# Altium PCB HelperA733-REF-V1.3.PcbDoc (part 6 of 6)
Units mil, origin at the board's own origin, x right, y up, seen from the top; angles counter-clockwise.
Board outline 5905.51 x 4133.86 mil, 2 copper layers (Top, Bottom), stack 12.7 mil thick; 446 components, 341 nets, 1706 pads, 1667 vias.
Unrouted connection lines stored in the file: 1382.
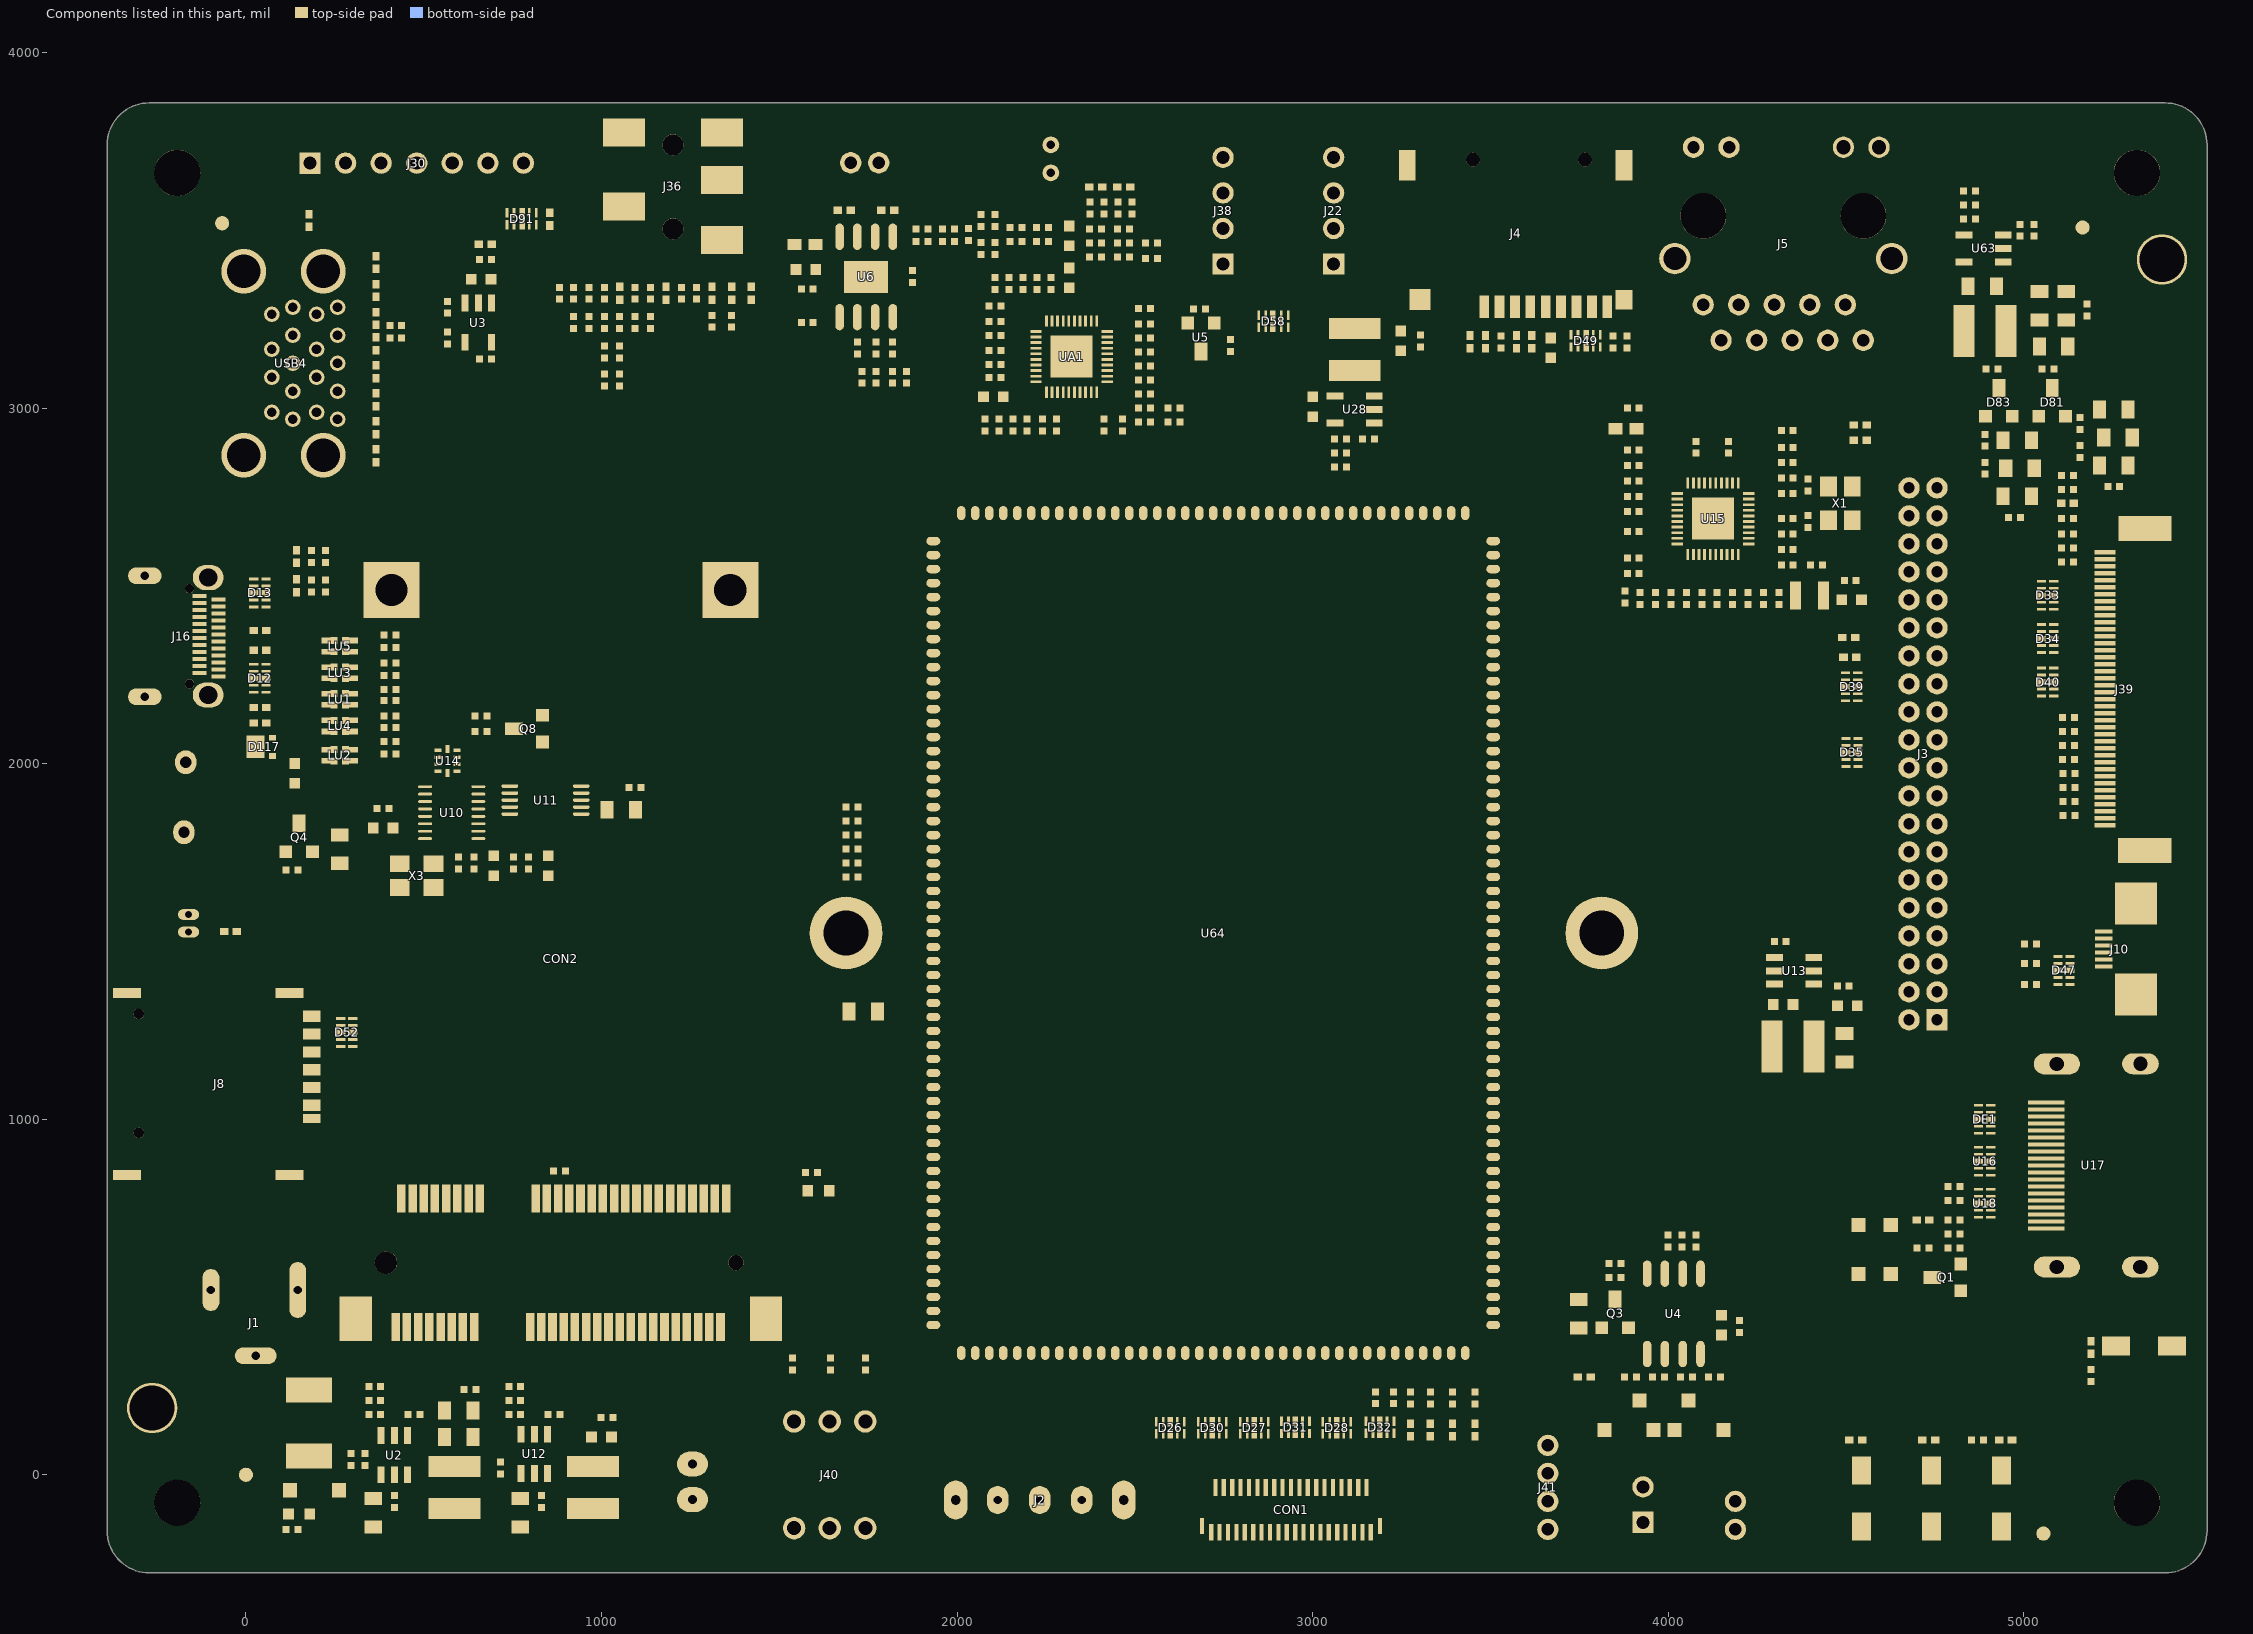
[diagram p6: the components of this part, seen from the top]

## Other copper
Top:
  region net DCIN: 433.07,19.69 429.13,23.62 401.57,23.62 397.64,19.69 397.64,-27.56 393.7,-31.5 314.96,-31.5 267.72,15.75 267.72,86.61 263.78,90.55 114.17,90.55 110.24,86.61 110.24,0 114.17,-3.94 204.72,-3.94 208.66,-7.87 208.66,-82.68 212.6,-86.61 385.83,-86.61 401.57,-70.87 429.13,-70.87 433.07,-66.93 433.07,19.69
  region net 5V: 688.64,900.16 688.64,845.23 748.73,845.23 748.73,900.16 688.64,900.16
  region net VCC-3V3: 3047.24,3192.91 3314.96,3192.91 3318.9,3196.85 3318.9,3255.91 3314.96,3259.84 3047.24,3259.84 3043.31,3255.91 3043.31,3196.85 3047.24,3192.91
  region net N17914651: 4918.31,3417.32 4918.31,3407.42 4957.1,3368.63 4957.1,3307.15 4918.31,3268.36 4918.31,3102.36 4922.24,3098.43 5060.04,3098.43 5063.98,3102.36 5063.98,3200.79 5060.04,3204.72 4997.05,3204.72 4993.11,3208.66 4993.11,3417.32 4989.17,3421.26 4922.24,3421.26 4918.31,3417.32
  region net 5V: 694.25,624.85 694.25,575.69 748.95,575.69 748.95,624.85 694.25,624.85
  region net REGOUT: 4195.66,2607.02 4191.66,2603.02 4191.66,2531.02 4207.66,2515.02 4315.66,2515.02 4331.66,2499.02 4331.66,2435.02 4335.66,2431.02 4367.66,2431.02 4371.66,2435.02 4371.66,2535.02 4363.66,2543.02 4233.66,2543.02 4223.66,2553.02 4223.66,2603.02 4219.66,2607.02 4195.66,2607.02
  region net N17914691: 4863.19,2992.13 4863.19,2917.32 4867.13,2913.39 4914.37,2913.39 4918.31,2909.45 4918.31,2885.83 4922.24,2881.89 4957.68,2881.89 4961.61,2885.83 4961.61,2940.94 4957.68,2944.88 4926.18,2944.88 4922.24,2948.82 4922.24,2992.13 4918.31,2996.06 4867.13,2996.06 4863.19,2992.13
  region net VCC-1V8: 2634.84,3295.15 2630.84,3291.15 2630.84,3223.15 2634.84,3219.15 2676.01,3219.15 2680.01,3223.15 2680.01,3291.15 2676.01,3295.15 2634.84,3295.15
  region net N5679088: 440.94,19.69 440.94,-122.05 444.88,-125.98 657.48,-125.98 661.42,-122.05 661.42,-66.93 657.48,-62.99 503.94,-62.99 500,-59.06 500,19.69 496.06,23.62 444.88,23.62 440.94,19.69
  region net AVDD10: 4423.66,2518.61 4419.66,2514.61 4419.66,2435.02 4423.66,2431.02 4503.66,2431.02 4507.66,2435.02 4507.66,2531.02 4503.66,2535.02 4475.66,2535.02 4471.66,2531.02 4471.66,2503.02 4467.66,2499.02 4463.66,2499.02 4459.66,2503.02 4459.66,2514.61 4455.66,2518.61 4423.66,2518.61
  region net VGH: 5142.72,2944.88 5142.72,2885.83 5146.65,2881.89 5189.96,2881.89 5193.9,2877.95 5193.9,2771.65 5197.83,2767.72 5245.08,2767.72 5249.02,2771.65 5249.02,2944.88 5245.08,2948.82 5146.65,2948.82 5142.72,2944.88
  region net N16925291: 4436,1388 4432,1392 4384,1392 4380,1388 4380,1132 4384,1128 4516,1128 4520,1132 4520,1188 4516,1192 4440,1192 4436,1196 4436,1388
  region net 5V: 4863.19,3145.67 4863.19,3417.32 4859.25,3421.26 4804.13,3421.26 4800.2,3417.32 4800.2,3145.67 4804.13,3141.73 4859.25,3141.73 4863.19,3145.67
  region net N17680063: 3149.61,3023.62 3153.54,3019.69 3192.91,3019.69 3196.85,3023.62 3196.85,3133.86 3192.91,3137.8 3047.24,3137.8 3043.31,3133.86 3043.31,3070.87 3047.24,3066.93 3145.67,3066.93 3149.61,3062.99 3149.61,3023.62
  region net VCC_4G: 905.51,-7.87 1295.28,-7.87 1299.21,-3.94 1299.21,350.39 1295.28,354.33 1133.86,354.33 1129.92,350.39 1129.92,181.1 1125.98,177.17 1023.62,177.17 1019.68,173.23 1019.68,129.92 1011.81,122.05 1011.81,66.93 1007.87,62.99 905.51,62.99 901.57,59.06 901.57,-3.94 905.51,-7.87
  region net VBUS-USB: 519.68,1803.15 523.62,1807.09 523.62,1814.96 519.68,1818.9 460.63,1818.9 437.01,1842.52 437.01,1874.02 417.32,1893.7 393.7,1893.7 389.76,1889.76 389.76,1807.09 393.7,1803.15 519.68,1803.15
  region net LED+: 5259.45,1851.32 5257.45,1853.32 5207.45,1853.32 5205.45,1851.32 5205.45,1811.32 5207.45,1809.32 5257.45,1809.32 5259.45,1811.32 5259.45,1851.32
  region net N17914681: 5071.85,3122.05 5071.85,3094.49 5060.04,3082.68 5060.04,3035.43 5063.98,3031.5 5119.09,3031.5 5123.03,3035.43 5123.03,3122.05 5119.09,3125.98 5075.79,3125.98 5071.85,3122.05
  region net VCC_4G: 1136.38,452.21 1136.38,379.56 1186.82,379.56 1186.82,452.21 1136.38,452.21
  region net N17914762: 5095.66,2991.02 5095.66,2964.34 5100,2960 5228,2960 5235.66,2967.66 5235.66,3019.02 5231.66,3023.02 5195.66,3023.02 5191.66,3019.02 5191.66,2999.02 5187.66,2995.02 5099.66,2995.02 5095.66,2991.02
  region net AVDD: 5079.72,3149.61 5083.66,3145.67 5189.96,3145.67 5193.9,3149.61 5193.9,3196.85 5189.96,3200.79 5154.53,3200.79 5150.59,3204.72 5150.59,3212.6 5154.53,3216.54 5189.96,3216.54 5193.9,3220.47 5193.9,3271.65 5016.73,3271.65 5012.8,3267.72 5012.8,3216.54 5016.73,3212.6 5075.79,3212.6 5079.72,3208.66 5079.72,3149.61
  region net LED+: 4456,1220 4548,1220 4552,1224 4552,1388 4548,1392 4508,1392 4504,1388 4504,1288 4500,1284 4456,1284 4452,1280 4452,1224 4456,1220
  region net AVDD33: 4039.66,2755.02 4043.66,2759.02 4043.66,2791.02 4039.66,2795.02 3992.98,2795.02 3960,2828 3960,2960 3956.98,2963.02 3887.66,2963.02 3883.66,2959.02 3883.66,2919.02 3908.15,2894.54 3908.15,2785.3 3910.42,2783.02 3919.66,2783.02 3947.66,2755.02 4039.66,2755.02
  region net 5V-IN: 1751.97,1275.59 1795.28,1275.59 1799.21,1279.53 1799.21,1377.95 1795.28,1381.89 1751.97,1381.89 1748.03,1377.95 1748.03,1279.53 1751.97,1275.59
  region net VBUS-USB: 94.49,2082.68 90.55,2086.61 66.93,2086.61 62.99,2082.68 62.99,1897.64 66.93,1893.7 153.54,1893.7 157.48,1897.64 157.48,1964.57 153.54,1968.5 98.43,1968.5 94.49,1972.44 94.49,2082.68
  region net VBUS1: 676.13,3275.59 680.07,3271.65 716.54,3271.65 720.47,3275.59 720.47,3472.44 716.54,3476.38 680.07,3476.38 676.13,3472.44 676.13,3275.59
  region net 5V: 515.75,66.93 511.81,62.99 511.81,-3.94 515.75,-7.87 677.17,-7.87 681.1,-3.94 681.1,251.97 677.17,255.91 637.8,255.91 633.86,251.97 633.86,228.35 594.49,188.98 594.49,70.87 590.55,66.93 515.75,66.93
  region net N179147341: 4863.19,3122.05 4863.19,3035.43 4867.13,3031.5 4949.8,3031.5 4953.74,3035.43 4953.74,3078.74 4949.8,3082.68 4910.43,3082.68 4906.5,3086.61 4906.5,3122.05 4902.56,3125.98 4867.13,3125.98 4863.19,3122.05
  region net N5680029: 102.36,200.79 240.16,200.79 244.09,204.72 244.09,602.36 240.16,606.3 102.36,606.3 98.43,602.36 98.43,204.72 102.36,200.79
  region net 5V: 3084,3016 3088,3020 3088,3056 3084,3060 3036,3060 3032,3064 3032,3100 3028,3104 2975.82,3104 2974.15,3102.33 2974.15,3024.9 2983.05,3016 3084,3016
  region net VGL: 4863.19,2901.57 4863.19,2838.58 4867.13,2834.65 4910.43,2834.65 4914.37,2830.71 4914.37,2681.1 4918.31,2677.17 4965.55,2677.17 4969.49,2681.1 4969.49,2866.14 4965.55,2870.08 4910.43,2870.08 4906.5,2874.02 4906.5,2901.57 4902.56,2905.51 4867.13,2905.51 4863.19,2901.57
  region net 5V: 1716.54,1336.06 1712.6,1340 1622.05,1340 1618.11,1336.06 1618.11,1259.94 1622.05,1256 1712.6,1256 1716.54,1259.94 1716.54,1336.06
  region net 5V: 2988.7,3193.77 2988.7,3121.77 3016.7,3121.77 3016.7,3193.77 2988.7,3193.77
  region net 5V: 4324,1388 4320,1392 4212,1392 4208,1388 4208,1132 4212,1128 4320,1128 4324,1132 4324,1388
  region net 5V-IN: 1917.32,1417.32 1917.32,1354.33 1921.26,1350.39 1976.38,1350.39 1980.31,1354.33 1980.31,1417.32 1976.38,1421.26 1921.26,1421.26 1917.32,1417.32
  region net DCIN: 680,-224 680,-248 756,-248 756,-224 680,-224
  region net DCIN: 830.71,27.56 826.77,31.5 795.28,31.5 791.34,27.56 791.34,-31.5 787.4,-35.43 695.94,-35.43 692,-39.37 692,-86.61 695.94,-90.55 807.09,-90.55 811.02,-86.61 811.02,-74.8 814.96,-70.87 842.52,-70.87 846.46,-66.93 846.46,-47.24 830.71,-31.5 830.71,27.56
  region net 5V: 681.1,3212.6 677.17,3208.66 677.17,3091.94 681.1,3088 740.09,3088 744.03,3091.94 744.03,3208.66 740.09,3212.6 681.1,3212.6
  region net N17177143: 838.58,27.56 838.58,-25.52 854.33,-41.27 854.33,-122.05 858.27,-125.98 1047.24,-125.98 1051.18,-122.05 1051.18,-66.93 1047.24,-62.99 893.7,-62.99 889.76,-59.06 889.76,27.56 885.83,31.5 842.52,31.5 838.58,27.56
Bottom:
  region net AVDD33: 3970.77,2953.26 3966.77,2957.26 3906.77,2957.26 3902.77,2953.26 3902.77,2841.26 3906.77,2837.26 3966.77,2837.26 3970.77,2841.26 3970.77,2953.26
  region net 5V: 691.98,648.04 691.98,581.49 749.2,581.49 749.2,648.04 691.98,648.04
  region net 5V: 708,3216 708,3096 712,3092 744,3092 748,3096 748,3172 752,3176 752,3216 748,3220 712,3220 708,3216
  region net 5V: 4196,1388 4196,1312 4200,1308 4268,1308 4272,1312 4272,1388 4268,1392 4200,1392 4196,1388
  region net 5V: 1622.05,1338.58 1618.11,1334.65 1618.11,1271.65 1622.05,1267.72 2467.56,1267.72 2471.49,1271.65 2471.49,1330.71 2467.56,1334.65 1992.13,1334.65 1980.31,1322.83 1746.43,1322.83 1730.68,1338.58 1622.05,1338.58
  region net 5V: 694.47,885.82 694.47,839.89 746.75,839.89 746.75,885.82 694.47,885.82
  region net DCIN: 676,-40 676,-244 680,-248 756,-248 760,-244 760,-40 756,-36 680,-36 676,-40
  region net 5V: 4801.1,3390.88 4801.1,3306.7 4828.66,3306.7 4828.66,3390.88 4801.1,3390.88
  region net 5V-IN: 1748.03,1334.65 1751.97,1330.71 1976.38,1330.71 1980.31,1334.65 1980.31,1413.39 1976.38,1417.32 1751.97,1417.32 1748.03,1413.39 1748.03,1334.65

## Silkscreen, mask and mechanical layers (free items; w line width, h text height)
Silkscreen Top:
  lines w5: 410,3470 410,3420 510,3420 510,3470 ; 500,2884 500,3110.24 ; 1830.71,1385.83 1850.39,1385.83 ; 1889.76,1366.14 1850.39,1366.14 1850.39,1405.51 1889.76,1405.51 ; 2710,2910 2660,2910 2660,3110 2710,3110 ; 2710,2910 2710,3110 ; 2710,2910 2810,2910 2810,3110 2710,3110 ; 2870,2910 2870,3110 ; 2870,2910 2970,2910 2970,3110 2870,3110 ; 2870,2910 2820,2910 2820,3110 2870,3110 ; 280,3470 630,3470 630,3570 280,3570 280,3470 ; 412,2884 412,3110.24 584,3110.24 584,2884 412,2884
  text "MIC" at 2372,3676 h25
  text "+" at 1677.17,3578.74 h25
  text "SPK" at 1708.66,3578.74 h25
  text "-" at 1791.34,3578.74 h25
  text "CS1" at 320,3480 h25 r90
  text "CLK" at 370,3480 h25 r90
  text "MOSI" at 420,3480 h25 r90
  text "MISO" at 470,3480 h25 r90
  text "CSO" at 520,3480 h25 r90
  text "GND" at 570,3480 h25 r90
  text "3.3V" at 620,3480 h25 r90
  text "SPI0" at 420,3430 h25
  text "Phone Jack" at 787.4,3409.45 h29.53
  text "TF" at 3356.61,3195.27 h29.53
  text "GND" at 2720,3070 h25
  text "GND" at 2880,3070 h25
  text "ETH 1000M" at 4257.75,3055.74 h29.53
  text "RX" at 2720,3020 h25
  text "RX" at 2880,3020 h25
  text "TX" at 2720,2970 h25
  text "TX" at 2880,2970 h25
  text "UART4" at 2700,2950 h25 r90
  text "UART3" at 2860,2950 h25 r90
  text "3.3V" at 2720,2920 h25
  text "3.3V" at 2880,2920 h25
  text "DN_U2.0" at 468,2904 h29.53 r90
  text "UP_U3.0" at 560,2904 h29.53 r90
  text "OTG" at -9.05,2548.39 h29.53 r90
  text "20250903" at 4310,1770 h78.74 r90
  text "LCD" at 5137.8,1716.54 h29.53 r90
  text "-" at -307.09,1637.8 h29.53 r270
  text "百杰科技" at 4110,1620 h196.85 r90
  text "CTP" at 5137.8,1539.37 h29.53 r90
  text "RTC" at -271.65,1519.69 h29.53 r90
  text "+" at -311.02,1503.94 h29.53 r270
  text "HelperBoard A733 V1.3" at 4220,1450 h86.61 r90
  text "5V" at 1795.28,1393.7 h25
  text "LCD" at 4880,1120 h29.53 r90
  text "SIM" at 275.05,892.49 h29.53 r90
  text "HDMI" at 4992.13,830.71 h29.53 r90
  text "4G" at 1686.58,784.93 h25
  text "DCIN_12V" at 227.57,435.33 h29.53 r90
  text "RESET" at 5288.44,244.17 h25
  text "LCD-SEL" at 1541.68,225.9 h29.53
  text "3.3V" at 3530,84 h25 r90
  text "ON/OFF" at 2147,78.21 h29.53
  text "KEY" at 4134.7,31.03 h25
  text "CAMERA" at 2871.05,23.79 h29.53
  text "+" at 1531.63,4.81 h25 r180
  text "GND" at 3530,-16 h25 r90
  text "+" at 3783.25,-40.92 h25 r90
  text "GND" at 4066.54,-70 h25 r90
  text "FEL" at 4658.42,-85.9 h29.53 r90
  text "RST" at 4855.39,-88.25 h29.53 r90
  text "PWR" at 5057.87,-90.76 h29.53 r90
  text "GND" at 3530,-110 h25 r90
  text "485" at 3785.12,-121.25 h25 r90
  text "-" at 3786.05,-156.75 h25 r90
  text "12V" at 3530,-210 h25 r90
  text "LRADC" at 4068.33,-229.87 h25 r90
Assembly Drawing Top:
  circle w10: c867.32,364.07 r82.68
  lines w1: 2562.58,3858.27 2562.61,3858.27 ; 3023.62,-275.59 3023.65,-275.59
  lines w10: -817.72,-275.59 2973.62,-275.59 ; -817.72,3858.27 2512.58,3858.27 ; -767.72,1723.84 -767.72,-275.59 ; -767.72,1858.84 -767.72,3858.27 ; -575.32,-78.74 -243.32,-78.74 ; -575.32,3661.42 -243.32,3661.42 ; -525.32,1706.94 -525.32,-78.74 ; -525.32,2078.31 -525.32,3661.42 ; -193.32,3711.42 -193.32,4032.45 ; 2359.86,3982.45 -193.32,3982.45 ; 2765.31,3982.45 5318.49,3982.45 ; 5318.49,3711.42 5318.49,4032.45 ; -767.72,-275.59 -742.72,-175.59 -792.72,-175.59 -767.72,-275.59 ; -767.72,3858.27 -792.72,3758.27 -742.72,3758.27 -767.72,3858.27 ; -525.32,-78.74 -500.32,21.26 -550.32,21.26 -525.32,-78.74 ; -525.32,3661.42 -550.32,3561.42 -500.32,3561.42 -525.32,3661.42 ; -193.32,3982.45 -93.32,3957.45 -93.32,4007.45 -193.32,3982.45 ; 5318.49,3982.45 5218.49,4007.45 5218.49,3957.45 5318.49,3982.45 ; 778.74,275.48 778.74,2834.54 4873.22,2834.54 4873.22,275.48 778.74,275.48 ; 4608.74,1091.48 4608.74,2963.48 4828.74,2963.48 4828.74,1091.48 4608.74,1091.48 ; 4628.74,1227.48 4628.74,2825.48 4802.74,2825.48 4802.74,1227.48 4628.74,1227.48
  text "140.0mm" at 2389.86,3944.95 h50
  text "105.0mm" at -940.44,1753.84 h50
  text "95.0mm" at -505.37,1736.94 h50 r90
